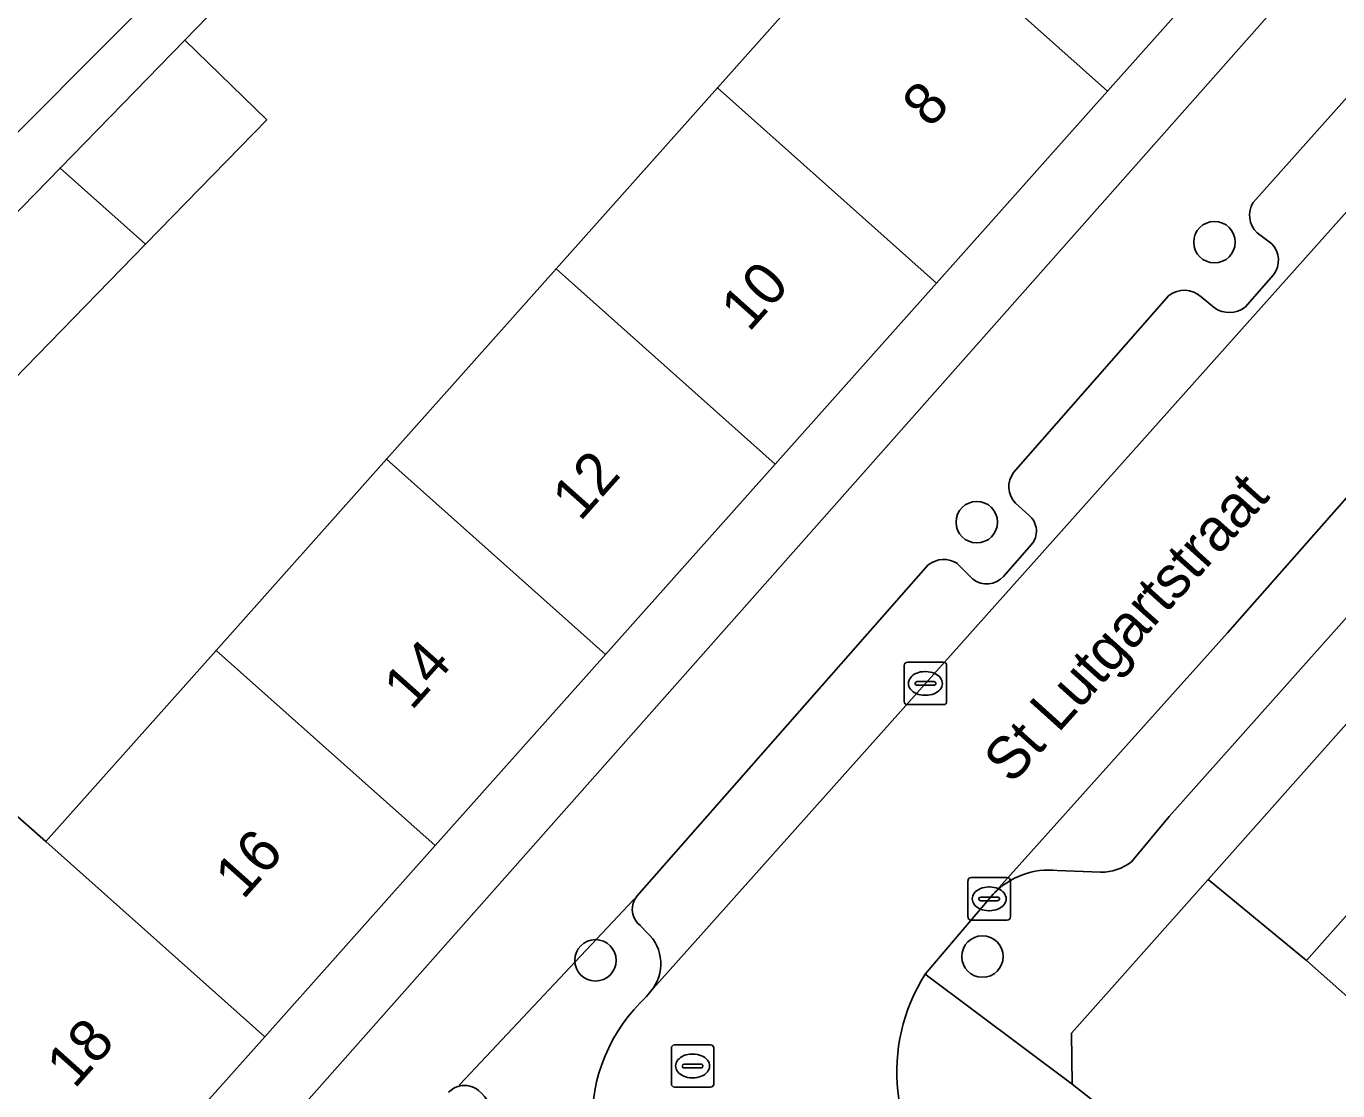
# Model space of a CAD drawing. Extents: x 162803 to 163818, y 381639 to 382475.
# Drawn here: x 162894.18 to 162925.14, y 382023.39 to 382048.5 of the extents above; entities that cross this region are included whole.
import ezdxf

# ---------------------------------------------------------------- set-up
doc = ezdxf.new("R2010")
doc.units = 0
for name, color, linetype in [('IMGEO_Boom', 7, 'Continuous'), ('IMGEO_Erf', 7, 'Continuous'), ('IMGEO_Groenvoorziening', 7, 'Continuous'), ('IMGEO_Kolk', 7, 'Continuous'), ('IMGEO_Openbare_ruimte_label', 7, 'Continuous'), ('IMGEO_Pand', 7, 'Continuous'), ('IMGEO_Pand_nummerreeks', 7, 'Continuous'), ('IMGEO_Parkeervlak_open', 7, 'Continuous'), ('IMGEO_Rijbaan_lokaal_open', 7, 'Continuous'), ('IMGEO_Rioolput', 7, 'Continuous'), ('IMGEO_Voetpad_open', 7, 'Continuous')]:
    doc.layers.add(name, color=color, linetype=linetype)

msp = doc.modelspace()

# ---------------------------------------------------------------- linework, layer by layer
at = {"layer": 'IMGEO_Boom'}
for centre in [(162922.226, 382043.408), (162916.617, 382036.802), (162907.619, 382026.464), (162916.751, 382026.553)]:
    msp.add_circle(centre, 0.489, dxfattribs=at)
at = {"layer": 'IMGEO_Erf'}
for points in [[(162923.62, 382051.368), (162919.703, 382046.973), (162915.664, 382042.443), (162911.858, 382038.173), (162907.855, 382033.683), (162903.833, 382029.17), (162899.812, 382024.661), (162895.703, 382020.051), (162897.033, 382018.87), (162897.226, 382019.086), (162898.37, 382020.378), (162939.702, 382067.058)], [(162948.951, 382058.608), (162922.075, 382028.37), (162924.398, 382026.461), (162928.379, 382030.947), (162932.179, 382035.23), (162935.991, 382039.525), (162940.234, 382044.307)], [(162900.392, 382050.712), (162897.925, 382048.178), (162899.86, 382046.295), (162897, 382043.358), (162893.61, 382039.877), (162891.676, 382041.761), (162889.752, 382039.785), (162891.686, 382037.901), (162888.561, 382034.691), (162886.543, 382036.489), (162885.566, 382035.485), (162887.501, 382033.602), (162884.227, 382030.239), (162888.693, 382026.299), (162892.789, 382030.894), (162894.644, 382029.268), (162898.664, 382033.778), (162902.686, 382038.29), (162906.69, 382042.781), (162910.495, 382047.05), (162914.534, 382051.581)], [(162882.791, 382048.99), (162880.847, 382047.126), (162880.021, 382047.987), (162876.926, 382045.015), (162873.5, 382041.726), (162872.86, 382042.393), (162871.249, 382040.847), (162869.163, 382038.844), (162869.766, 382038.215), (162866.707, 382035.277), (162874.031, 382029.569), (162877.926, 382033.935), (162880.699, 382037.043), (162882.864, 382035.111), (162887.58, 382039.225), (162885.827, 382040.857), (162888.176, 382043.381), (162891.004, 382046.42), (162892.757, 382044.788), (162897.236, 382049.27)]]:
    msp.add_lwpolyline(points, dxfattribs=at)
at = {"layer": 'IMGEO_Groenvoorziening'}
msp.add_lwpolyline([(162929.595, 382021.849), (162924.398, 382026.461), (162922.075, 382028.37), (162918.856, 382024.749), (162918.865, 382023.545), (162934.177, 382011.519), (162936.109, 382014.006), (162929.716, 382019.448)], dxfattribs=at)
for centre, radius, start, end in [((162904.528, 382022.991), 0.521, 102.2518, 135.9679), ((162904.529, 382022.978), 0.534, 51.5526, 102.0814), ((162904.137, 382022.561), 1.105, 7.2549, 49.0611)]:
    msp.add_arc(centre, radius, start, end, dxfattribs=at)
at = {"layer": 'IMGEO_Kolk'}
for p, q in [((162914.905, 382032.571), (162914.905, 382033.423)), ((162914.98, 382033.497), (162915.832, 382033.497)), ((162915.906, 382033.423), (162915.906, 382032.571)), ((162915.393, 382033.277), (162915.418, 382033.277)), ((162915.164, 382032.991), (162915.164, 382033.003)), ((162915.602, 382032.954), (162915.204, 382032.954)), ((162915.207, 382033.04), (162915.605, 382033.04)), ((162915.648, 382033.003), (162915.648, 382032.991)), ((162915.832, 382032.497), (162914.98, 382032.497)), ((162915.416, 382032.717), (162915.391, 382032.717)), ((162916.41, 382027.489), (162916.41, 382028.341)), ((162916.485, 382028.415), (162917.337, 382028.415)), ((162916.898, 382028.195), (162916.923, 382028.195)), ((162917.411, 382028.341), (162917.411, 382027.489)), ((162916.669, 382027.909), (162916.669, 382027.921)), ((162917.107, 382027.872), (162916.709, 382027.872)), ((162916.712, 382027.958), (162917.11, 382027.958)), ((162917.153, 382027.921), (162917.153, 382027.909)), ((162916.921, 382027.635), (162916.896, 382027.635)), ((162917.337, 382027.415), (162916.485, 382027.415))]:
    msp.add_line(p, q, dxfattribs=at)
for points in [[(162914.905, 382032.571), (162914.905, 382033.423)], [(162914.98, 382033.497), (162915.832, 382033.497)], [(162915.906, 382033.423), (162915.906, 382032.571)], [(162915.832, 382032.497), (162914.98, 382032.497)], [(162916.41, 382027.489), (162916.41, 382028.341)], [(162916.485, 382028.415), (162917.337, 382028.415)], [(162917.411, 382028.341), (162917.411, 382027.489)], [(162917.337, 382027.415), (162916.485, 382027.415)]]:
    msp.add_lwpolyline(points, dxfattribs=at)
for centre, radius, start, end in [((162914.982, 382033.421), 0.0765, 91.552, 178.448), ((162914.982, 382033.421), 0.0765, 91.552, 178.448), ((162915.83, 382033.421), 0.0765, 1.552, 88.448), ((162915.83, 382033.421), 0.0765, 1.552, 88.448), ((162915.204, 382033), 0.0403, 85.8775, 175.7526), ((162915.201, 382032.99), 0.0366, 178.938, 274.7102), ((162915.605, 382032.997), 0.043, 264.8664, 352.4533), ((162915.609, 382033.002), 0.0386, 1.7309, 96.639), ((162914.982, 382032.573), 0.0765, 181.552, 268.448), ((162914.982, 382032.573), 0.0765, 181.552, 268.448), ((162915.83, 382032.573), 0.0765, 271.552, 358.448), ((162915.83, 382032.573), 0.0765, 271.552, 358.448), ((162916.487, 382028.339), 0.0765, 91.552, 178.448), ((162916.487, 382028.339), 0.0765, 91.552, 178.448), ((162917.335, 382028.339), 0.0765, 1.552, 88.448), ((162917.335, 382028.339), 0.0765, 1.552, 88.448), ((162916.709, 382027.918), 0.0403, 85.8775, 175.7526), ((162916.706, 382027.908), 0.0366, 178.938, 274.7102), ((162917.11, 382027.915), 0.043, 264.8664, 352.4533), ((162917.114, 382027.92), 0.0386, 1.7309, 96.639), ((162916.487, 382027.491), 0.0765, 181.552, 268.448), ((162916.487, 382027.491), 0.0765, 181.552, 268.448), ((162917.335, 382027.491), 0.0765, 271.552, 358.448), ((162917.335, 382027.491), 0.0765, 271.552, 358.448)]:
    msp.add_arc(centre, radius, start, end, dxfattribs=at)
for centre, major_axis, ratio, start_param, end_param in [((162915.392, 382032.997), (-0.387, 0.002), 0.722429, 4.712389, 7.853982), ((162915.417, 382032.997), (-0.39, 0.002), 0.717154, 1.570796, 4.712389), ((162916.897, 382027.915), (-0.387, 0.002), 0.722429, 4.712389, 7.853982), ((162916.922, 382027.915), (-0.39, 0.002), 0.717154, 1.570796, 4.712389)]:
    msp.add_ellipse(centre, major_axis=major_axis, ratio=ratio, start_param=start_param, end_param=end_param, dxfattribs=at)
at = {"layer": 'IMGEO_Pand'}
for points in [[(162923.62, 382051.368), (162918.452, 382055.975), (162914.534, 382051.581), (162919.703, 382046.973)], [(162915.664, 382042.443), (162919.703, 382046.973), (162914.534, 382051.581), (162910.495, 382047.05)], [(162897.925, 382048.178), (162894.982, 382045.156), (162897, 382043.358), (162899.86, 382046.295)], [(162915.664, 382042.443), (162910.495, 382047.05), (162906.69, 382042.781), (162911.858, 382038.173)], [(162897, 382043.358), (162894.982, 382045.156), (162891.676, 382041.761), (162893.61, 382039.877)], [(162907.855, 382033.683), (162911.858, 382038.173), (162906.69, 382042.781), (162902.686, 382038.29)], [(162907.855, 382033.683), (162902.686, 382038.29), (162898.664, 382033.778), (162903.833, 382029.17)], [(162894.644, 382029.268), (162899.812, 382024.661), (162903.833, 382029.17), (162898.664, 382033.778)], [(162933.576, 382026.335), (162928.379, 382030.947), (162924.398, 382026.461), (162929.595, 382021.849), (162932.914, 382025.589)], [(162894.644, 382029.268), (162892.789, 382030.894), (162888.693, 382026.299), (162890.534, 382024.658), (162891.971, 382023.378), (162895.703, 382020.051), (162899.812, 382024.661)]]:
    msp.add_lwpolyline(points, close=True, dxfattribs=at)
at = {"layer": 'IMGEO_Parkeervlak_open'}
for points in [[(162908.926, 382025.738), (162940.419, 382061.006)], [(162938.019, 382051.566), (162937.653, 382051.145), (162932.733, 382045.731), (162929.723, 382042.344), (162922.534, 382034.193), (162917.005, 382028.023)], [(162929.609, 382051.596), (162923.139, 382044.343)], [(162923.232, 382043.631), (162923.579, 382043.371)], [(162923.618, 382042.638), (162922.95, 382041.873)], [(162921.15, 382042.148), (162917.488, 382037.977)], [(162922.229, 382041.857), (162921.913, 382042.117)], [(162920.269, 382028.791), (162921.155, 382029.858), (162930.725, 382040.584), (162929.979, 382041.25)], [(162917.531, 382037.248), (162917.848, 382036.965)], [(162917.903, 382036.269), (162917.251, 382035.524)], [(162915.469, 382035.792), (162908.602, 382027.984)], [(162916.525, 382035.457), (162916.165, 382035.823)], [(162918.518, 382028.583), (162919.54, 382028.543)], [(162908.678, 382027.282), (162908.842, 382027.115)]]:
    msp.add_lwpolyline(points, dxfattribs=at)
for centre, radius, start, end in [((162923.619, 382044.044), 0.565, 148.0194, 226.864), ((162923.175, 382042.982), 0.561, 322.1872, 43.904), ((162921.514, 382041.693), 0.582, 46.7126, 128.6342), ((162922.578, 382042.362), 0.614, 235.3103, 307.2323), ((162917.932, 382037.637), 0.559, 142.5992, 224.1522), ((162917.539, 382036.59), 0.486, 318.5713, 50.4652), ((162915.838, 382035.331), 0.591, 56.4236, 128.677), ((162916.852, 382035.885), 0.539, 232.6818, 317.8636), ((162919.551, 382029.705), 1.162, 269.4431, 308.1327), ((162918.317, 382026.803), 1.791, 83.5486, 137.073), ((162908.967, 382027.669), 0.482, 152.15, 233.2642), ((162909.012, 382027.635), 0.538, 139.6088, 151.2661), ((162908.16, 382026.382), 1.001, 319.9478, 47.0339)]:
    msp.add_arc(centre, radius, start, end, dxfattribs=at)
at = {"layer": 'IMGEO_Rijbaan_lokaal_open'}
for points in [[(162947.554, 382062.095), (162943.583, 382064.624), (162940.419, 382061.006), (162908.926, 382025.738), (162908.824, 382025.608)], [(162915.402, 382026.137), (162917.005, 382028.023), (162922.534, 382034.193), (162929.723, 382042.344), (162932.733, 382045.731), (162937.653, 382051.145), (162938.019, 382051.566), (162938.744, 382052.402), (162947.554, 382062.095)]]:
    msp.add_lwpolyline(points, dxfattribs=at)
for centre, radius, start, end in [((162919.015, 382023.836), 4.284, 147.5103, 224.8439), ((162911.525, 382022.674), 3.988, 132.6367, 231.5978)]:
    msp.add_arc(centre, radius, start, end, dxfattribs=at)
at = {"layer": 'IMGEO_Rioolput'}
for p, q in [((162909.41, 382023.546), (162909.41, 382024.398)), ((162909.485, 382024.472), (162910.337, 382024.472)), ((162910.411, 382024.398), (162910.411, 382023.546)), ((162909.898, 382024.252), (162909.923, 382024.252)), ((162909.669, 382023.966), (162909.669, 382023.978)), ((162910.107, 382023.929), (162909.709, 382023.929)), ((162909.712, 382024.015), (162910.11, 382024.015)), ((162910.153, 382023.978), (162910.153, 382023.966)), ((162910.337, 382023.472), (162909.485, 382023.472)), ((162909.921, 382023.692), (162909.896, 382023.692))]:
    msp.add_line(p, q, dxfattribs=at)
for points in [[(162909.41, 382023.546), (162909.41, 382024.398)], [(162909.485, 382024.472), (162910.337, 382024.472)], [(162910.411, 382024.398), (162910.411, 382023.546)], [(162910.337, 382023.472), (162909.485, 382023.472)]]:
    msp.add_lwpolyline(points, dxfattribs=at)
for centre, radius, start, end in [((162909.487, 382024.396), 0.0765, 91.552, 178.448), ((162909.487, 382024.396), 0.0765, 91.552, 178.448), ((162910.335, 382024.396), 0.0765, 1.552, 88.448), ((162910.335, 382024.396), 0.0765, 1.552, 88.448), ((162909.709, 382023.975), 0.0403, 85.8775, 175.7526), ((162909.706, 382023.965), 0.0366, 178.938, 274.7102), ((162910.11, 382023.972), 0.043, 264.8664, 352.4533), ((162910.114, 382023.977), 0.0386, 1.7309, 96.639), ((162909.487, 382023.548), 0.0765, 181.552, 268.448), ((162909.487, 382023.548), 0.0765, 181.552, 268.448), ((162910.335, 382023.548), 0.0765, 271.552, 358.448), ((162910.335, 382023.548), 0.0765, 271.552, 358.448)]:
    msp.add_arc(centre, radius, start, end, dxfattribs=at)
for centre, major_axis, ratio, start_param, end_param in [((162909.897, 382023.972), (-0.387, 0.002), 0.722429, 4.712389, 7.853982), ((162909.922, 382023.972), (-0.39, 0.002), 0.717154, 1.570796, 4.712389)]:
    msp.add_ellipse(centre, major_axis=major_axis, ratio=ratio, start_param=start_param, end_param=end_param, dxfattribs=at)
at = {"layer": 'IMGEO_Voetpad_open'}
for points in [[(162940.419, 382061.006), (162943.583, 382064.624), (162939.702, 382067.058), (162898.37, 382020.378), (162900.498, 382018.497)], [(162917.005, 382028.023), (162915.402, 382026.137), (162918.865, 382023.545), (162918.856, 382024.749), (162922.075, 382028.37), (162948.951, 382058.608)], [(162923.139, 382044.343), (162929.609, 382051.596)], [(162891.676, 382041.761), (162894.982, 382045.156), (162897.925, 382048.178), (162900.392, 382050.712)], [(162897.236, 382049.27), (162892.757, 382044.788)], [(162923.579, 382043.371), (162923.232, 382043.631)], [(162922.95, 382041.873), (162923.618, 382042.638)], [(162917.488, 382037.977), (162921.15, 382042.148)], [(162921.913, 382042.117), (162922.229, 382041.857)], [(162929.979, 382041.25), (162930.725, 382040.584), (162921.155, 382029.858), (162920.269, 382028.791)], [(162917.848, 382036.965), (162917.531, 382037.248)], [(162917.251, 382035.524), (162917.903, 382036.269)], [(162908.602, 382027.984), (162915.469, 382035.792)], [(162916.165, 382035.823), (162916.525, 382035.457)], [(162919.54, 382028.543), (162918.518, 382028.583)], [(162904.417, 382023.5), (162904.421, 382023.535), (162908.519, 382027.895), (162908.54, 382027.894)], [(162908.54, 382027.894), (162908.519, 382027.895), (162904.421, 382023.535), (162904.417, 382023.5)], [(162908.842, 382027.115), (162908.678, 382027.282)], [(163000, 381959.74), (162977.939, 381977.029), (162975.634, 381978.836), (162969.071, 381983.988), (162948.843, 382000), (162937.978, 382008.533), (162936.637, 382009.587), (162936.523, 382009.676), (162934.177, 382011.519), (162918.865, 382023.545), (162915.402, 382026.137)], [(162908.824, 382025.608), (162908.926, 382025.738)]]:
    msp.add_lwpolyline(points, dxfattribs=at)
for centre, radius, start, end in [((162923.619, 382044.044), 0.565, 148.0194, 226.864), ((162923.175, 382042.982), 0.561, 322.1872, 43.904), ((162921.514, 382041.693), 0.582, 46.7126, 128.6342), ((162922.578, 382042.362), 0.614, 235.3103, 307.2323), ((162917.932, 382037.637), 0.559, 142.5992, 224.1522), ((162917.539, 382036.59), 0.486, 318.5713, 50.4652), ((162915.838, 382035.331), 0.591, 56.4236, 128.677), ((162916.852, 382035.885), 0.539, 232.6818, 317.8636), ((162919.551, 382029.705), 1.162, 269.4431, 308.1327), ((162918.317, 382026.803), 1.791, 83.5486, 137.073), ((162908.967, 382027.669), 0.482, 152.15, 233.2642), ((162909.012, 382027.635), 0.538, 139.6088, 151.2661), ((162908.16, 382026.382), 1.001, 319.9478, 47.0339), ((162919.015, 382023.836), 4.284, 147.5103, 224.8439), ((162911.525, 382022.674), 3.988, 132.6367, 231.5978), ((162904.528, 382022.991), 0.521, 102.2518, 135.9679), ((162904.529, 382022.978), 0.534, 51.5526, 102.0814), ((162904.137, 382022.561), 1.105, 7.2549, 49.0611)]:
    msp.add_arc(centre, radius, start, end, dxfattribs=at)

# ---------------------------------------------------------------- texts
at = {"layer": 'IMGEO_Openbare_ruimte_label'}
msp.add_text('St Lutgartstraat', height=1, rotation=48, dxfattribs=at).set_placement((162917.443, 382030.595))
at = {"layer": 'IMGEO_Pand_nummerreeks'}
for s, rotation, p in [('8', 48.2843, (162915.525, 382046.073)), ('10', 48.2843, (162911.24, 382041.265)), ('12', 48.2843, (162907.257, 382036.798)), ('14', 48.2843, (162903.28, 382032.337)), ('16', 48.2843, (162899.301, 382027.874)), ('18', 48.2832, (162895.325, 382023.412))]:
    msp.add_text(s, height=1, rotation=rotation, dxfattribs=at).set_placement(p)

doc.saveas('drawing.dxf')
